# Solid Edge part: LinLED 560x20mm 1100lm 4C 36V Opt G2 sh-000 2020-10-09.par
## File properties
Author: robert.pupel
Template: iso metric part.par
Last saved by: robert.pupel
Revision: 2
Application: Solid Edge
Gęstość: 0,000 kg/m^3
Dokładność: 0,990
Username: robert.pupel
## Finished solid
Body 1: solid body, 1414 faces, 3632 edges, 2288 vertices.
  Faces by surface: plane 822, cylinder 272, spline 192, cone 60, sphere 32, torus 20, spun 16
  Edges by curve: line 2376, curve on surface 648, circle 368, ellipse 132, spline 100, intersection 8
Bounding box of the edges (mm; curved faces can reach further): 560.000 x 4.450 x 20.000, from (-140, -3.45, -10) to (420, 1, 10).
Cylindrical faces by radius (mm): R0.2 x92, R0.2169 x12, R0.25 x24, R0.3373 x12, R0.4 x16, R0.4006 x4, R0.4008 x4, R0.525 x4, R0.6 x40, R1 x16, R1.1 x8, R1.2 x20, R2.15 x20
Conical faces (half-angle, radius in mm at the cone's reference point): 0.5 deg R0.5056 x8, 0.5 deg R1.0082 x8, 1 deg R0.5511 x4, 10 deg R0.2132 x8, 10 deg R0.4132 x8, 18.8604 deg R1.0669 x8, 27.363 deg R0.6214 x4, 45 deg R0.575 x4, 45 deg R0.625 x8
Toroidal faces (ring radius, tube radius in mm): R0.8 r0.2 x8, R0.8522 r0.3 x4, R0.9002 r0.2 x4, R0.9018 r0.2 x4
Spherical faces by radius (mm): R0.2 x24, R0.6 x8
Planar faces by outward normal: +x 99, +y 17, +z 91, -x 99, -y 121, -z 91, oblique 304
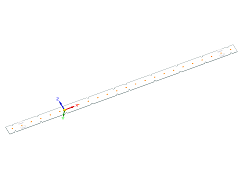
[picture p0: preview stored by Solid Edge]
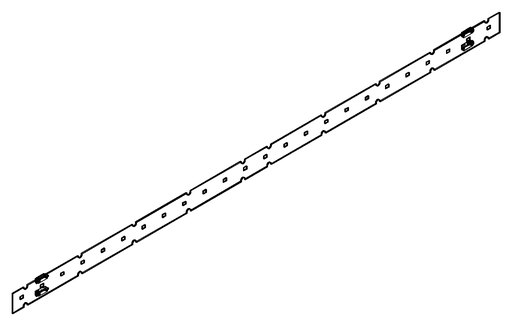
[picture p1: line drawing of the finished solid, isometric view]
